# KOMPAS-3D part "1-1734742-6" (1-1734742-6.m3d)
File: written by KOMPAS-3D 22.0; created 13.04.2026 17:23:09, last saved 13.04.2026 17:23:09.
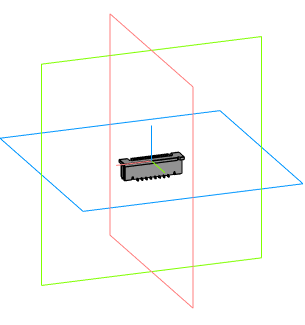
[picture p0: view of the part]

Document properties: Автор: Andrey; Полное имя файла: C:\Users\User1\Documents\1-1734742-6.m3d

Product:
- Part/product: 1-1734742-6
    Комментарий: PART-1-1734742-6-DESC

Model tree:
1. Операция без истории:1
